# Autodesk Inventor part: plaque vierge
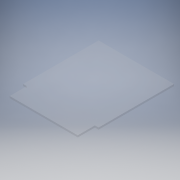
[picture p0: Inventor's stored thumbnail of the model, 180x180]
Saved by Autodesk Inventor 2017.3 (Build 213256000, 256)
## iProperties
Part Number: plaque vierge
Material: Générique
Document SubType Name: Modeling
Designer: ficho
Density: 1 g/cm^3
Appearance: Transparent - Clair
Author: ficho
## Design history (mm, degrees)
sketch "Esquisse1"
  geometry: L1 (123, 0)-(123, 123); L2 (123, 123)-(0, 123); L3 (0, 123)-(0, 0); L4 (117, 0)-(117, -28); L5 (117, -28)-(6, -28); L6 (6, -28)-(6, 0); L7 (0, 0)-(6, 0); L8 (117, 0)-(123, 0)
  constraints: 16 end point, 4 parallel, 2 horizontal, 2 perpendicular
  dimensions: "d0" = 123 distance of L2.end L1.end; "d1" = 123 distance of L1.end L1.start; "d2" = 6 distance between parallel lines of L6 L3; "d3" = 6 distance between parallel lines of L4 L1; "d4" = 28 distance between parallel lines of L7 L5
extrude "Extrusion1" new body sketch "Esquisse1" distance "d5" = 3; taper "d6" = 0 deg
sketch "Esquisse2"
  geometry: L1 (0, 0)-(0, 123) reference; L2 (0, 123)-(-123, 123) reference; L3 (-123, 123)-(-123, 0) reference; L4 (-123, 0)-(-117, 0) reference; L5 (-117, 0)-(-117, -28) reference; L6 (-117, -28)-(-6, -28) reference; L7 (-6, -28)-(-6, 0) reference; L8 (-6, 0)-(0, 0) reference; C1 r 1.5 at (-112, -14); C2 r 1.5 at (-11, -14); 1 further point
  constraints: 2 centre point
  dimensions: "d7" = 3 diameter of C1; "d8" = 3 diameter of C2 (= d7); "d9" = 5 distance from line of C1.centre L5; "d10" = 5 distance from line of L7 C2.centre (= d9)
extrude "Extrusion2" cut sketch "Esquisse2" stored distance "d11" = 3; taper "d12" = 0 deg
fillet "Congé1" dims "d13" = 10
node "Solide1"
node "Boucle projetée1"
